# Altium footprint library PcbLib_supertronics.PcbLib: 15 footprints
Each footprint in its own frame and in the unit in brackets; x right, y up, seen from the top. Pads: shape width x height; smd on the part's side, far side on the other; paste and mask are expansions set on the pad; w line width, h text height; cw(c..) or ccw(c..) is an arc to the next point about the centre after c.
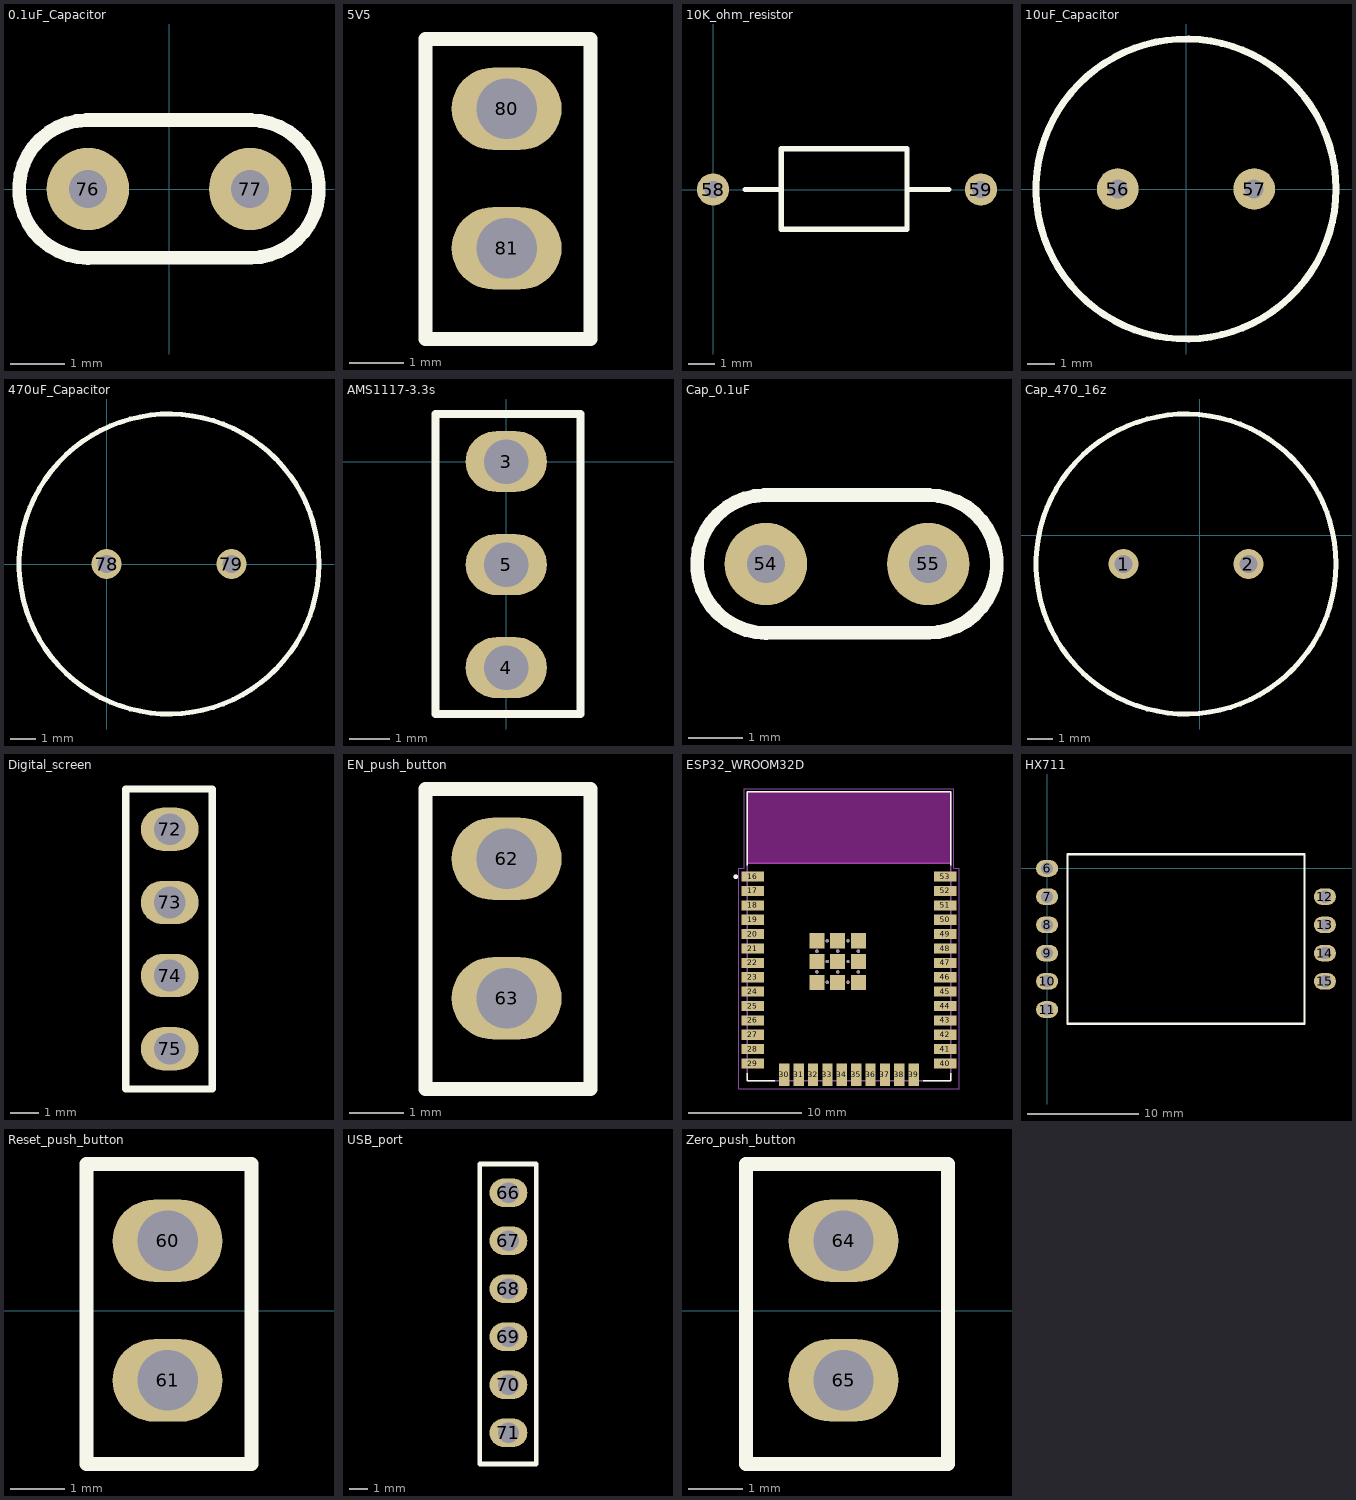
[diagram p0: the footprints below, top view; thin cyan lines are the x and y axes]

## 0.1uF_Capacitor [mm]
pads (2):
  round 1.524 hole 0.7: 76(-1.5,0) 77(1.5,0)
Top Overlay:
  lines w0.254: -1.548,-1.273 1.521,-1.273 ; -1.5,-1.274 cw(c-1.5,0) -1.524,1.274 1.52,1.274 ; 1.5,-1.274 ccw(c1.5,0) 1.5,1.274

## 5V5 [mm]
pads (2):
  oval 2x1.5 hole 1.1: 80(13.843,-2.54) 81(13.843,-5.08)
Top Overlay:
  lines w0.254: 12.367,-6.731 15.367,-6.731 15.367,-1.27 12.367,-1.27 12.367,-6.731

## 10K_ohm_resistor [mm] "Resistor"
pads (2):
  round 1.2 hole 0.65: 58(0,0) 59(10,0)
Top Overlay:
  lines w0.2: 1.2,0 2.54,0 ; 7.366,0 8.8,0 ; 2.54,0 2.54,1.524 7.239,1.524 7.239,-1.484 6.731,-1.484 5.683,-1.484 3.588,-1.484 2.54,-1.484 2.54,0

## 10uF_Capacitor [mm]
height 16
pads (2):
  round 1.524 hole 0.7: 56(-2.5,0) 57(2.5,0)
Top Overlay:
  circle w0.254: c0,0 r5.5

## 470uF_Capacitor [mm] "470 µF 16 V Aluminum Electrolytic Capacitors Radial, Can 9000 Hrs @ 105°C"
height 16
pads (2):
  round 1.2 hole 0.7: 78(0,0) 79(5,0)
Top Overlay:
  circle w0.2: c2.5,0 r6

## AMS1117-3.3s [mm]
height 20
pads (3):
  oval 2x1.5 hole 1.1: 3(0,0) 4(0,-5.08) 5(0,-2.54)
Top Overlay:
  lines w0.2: -1.748,-6.223 1.835,-6.223 1.835,1.173 0.939,1.173 -0.852,1.173 -1.748,1.173 -1.748,-6.223

## Cap_0.1uF [mil]
pads (2):
  round 60 hole 27.56: 54(555.94,160) 55(674.06,160)
Top Overlay:
  lines w10: 554.05,109.87 674.87,109.87 ; 555.94,109.83 cw(c555.94,160) 555,210.16 674.84,210.16 ; 674.06,109.86 ccw(c674.06,160) 674.06,210.14

## Cap_470_16z [mm]
pads (2):
  round 1.2 hole 0.7: 1(-3.048,-1.143) 2(1.952,-1.143)
Top Overlay:
  circle w0.2: c-0.548,-1.143 r6

## Digital_screen [mm] "Screen"
height 8.5
pads (4):
  oval 2x1.5 hole 1.1: 72(98.044,15.875) 73(98.044,13.335) 74(98.044,10.795) 75(98.044,8.255)
Top Overlay:
  lines w0.254: 96.52,6.858 99.52,6.858 99.52,17.272 96.52,17.272 96.52,6.858

## EN_push_button [mm] "EN"
height 8.5
pads (2):
  oval 2x1.5 hole 1.1: 62(96.647,-46.609) 63(96.647,-49.149)
Top Overlay:
  lines w0.254: 95.171,-50.8 98.171,-50.8 98.171,-45.339 95.171,-45.339 95.171,-50.8

## ESP32_WROOM32D [mm]
height 3.2
pads (59):
  rect 2x0.9 smd: 16(-126.483,-475.181) 17(-126.483,-476.451) 18(-126.483,-477.721) 19(-126.483,-478.991) 20(-126.483,-480.261) 21(-126.483,-481.531) 22(-126.483,-482.801) 23(-126.483,-484.071) 24(-126.483,-485.341) 25(-126.483,-486.611) 26(-126.483,-487.881) 27(-126.483,-489.151) 28(-126.483,-490.421) 29(-126.483,-491.691) 40(-109.483,-491.691) 41(-109.483,-490.421) 42(-109.483,-489.151) 43(-109.483,-487.881) 44(-109.483,-486.611) 45(-109.483,-485.341) 46(-109.483,-484.071) 47(-109.483,-482.801) 48(-109.483,-481.531) 49(-109.483,-480.261) 50(-109.483,-478.991) 51(-109.483,-477.721) 52(-109.483,-476.451) 53(-109.483,-475.181)
  rect 0.9x2 smd: 30(-123.698,-492.691) 31(-122.428,-492.691) 32(-121.158,-492.691) 33(-119.888,-492.691) 34(-118.618,-492.691) 35(-117.348,-492.691) 36(-116.078,-492.691) 37(-114.808,-492.691) 38(-113.538,-492.691) 39(-112.268,-492.691)
  rect 1.33x1.33 smd: 39_1(-120.818,-480.846) 39_2(-118.983,-480.846) 39_3(-117.148,-480.846) 39_4(-120.818,-482.681) 39_5(-118.983,-482.681) 39_6(-117.148,-482.681) 39_7(-120.818,-484.516) 39_8(-118.983,-484.516) 39_9(-117.148,-484.516)
  round 0.3 hole 0.3 unplated: 39_10(-119.9,-480.846) 39_11(-118.065,-480.846) 39_12(-120.818,-481.763) 39_13(-118.983,-481.763) 39_14(-117.148,-481.763) 39_15(-119.9,-482.681) 39_16(-118.065,-482.681) 39_17(-120.818,-483.598) 39_18(-118.983,-483.598) 39_19(-117.148,-483.598) 39_20(-119.9,-484.516) 39_21(-118.065,-484.516)
Top Overlay:
  circle w0.2: c-127.983,-475.191 r0.1
  lines w0.127: -126.983,-492.541 -126.983,-493.191 -124.533,-493.191 ; -126.983,-474.191 -126.983,-467.691 -108.983,-467.691 -108.983,-474.191 ; -111.433,-493.191 -108.983,-493.191 -108.983,-492.541
Keep-Out Layer:
  region: -108.983,-473.991 -126.983,-473.991 -126.983,-467.691 -108.983,-467.691
Mechanical 13:
  circle w0.2: c-127.983,-475.191 r0.1
  lines w0.127: -126.983,-473.991 -126.983,-493.191 -108.983,-493.191 -108.983,-473.991 ; -126.983,-473.991 -126.983,-467.691 -108.983,-467.691 -108.983,-473.991 ; -126.983,-473.991 -108.983,-473.991
  text "ANTENNA" at -123.983,-471.441 h1.78
Mechanical 15:
  lines w0.05: -127.733,-493.941 -108.233,-493.941 -108.233,-474.441 -108.733,-474.441 -108.733,-467.441 -127.233,-467.441 -127.233,-474.441 -127.733,-474.441 -127.733,-493.941
3D body "step_temp.STEP": height 3.25, standoff 0, extent -126.983,-493.191 -108.983,-467.691

## HX711 [mm]
pads (10):
  oval 2x1.5 hole 1.1: 6(0,0) 7(0,-2.54) 8(0,-5.08) 9(0,-7.62) 10(0,-10.16) 11(0,-12.7) 12(25,-2.54) 13(25,-5.08) 14(25,-7.62) 15(25,-10.16)
Top Overlay:
  lines w0.2: 13.081,1.27 1.835,1.27 1.835,-13.97 23.165,-13.97 23.165,1.27 13.135,1.27

## Reset_push_button [mm] "Reset"
height 8.5
pads (2):
  oval 2x1.5 hole 1.1: 60(61.341,1.268) 61(61.341,-1.272)
Top Overlay:
  lines w0.254: 59.865,-2.794 62.865,-2.794 62.865,2.667 59.865,2.667 59.865,-2.794

## USB_port [mm] "USB"
height 8.5
pads (6):
  oval 2x1.5 hole 1.1: 66(98.044,15.875) 67(98.044,13.335) 68(98.044,10.795) 69(98.044,8.255) 70(98.044,5.715) 71(98.044,3.175)
Top Overlay:
  lines w0.254: 96.52,1.524 99.52,1.524 99.52,17.399 96.52,17.399 96.52,1.524

## Zero_push_button [mm] "Zero"
height 8.5
pads (2):
  oval 2x1.5 hole 1.1: 64(61.342,1.27) 65(61.342,-1.27)
Top Overlay:
  lines w0.254: 59.564,-2.794 63.247,-2.794 63.247,2.667 59.564,2.667 59.564,-2.794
